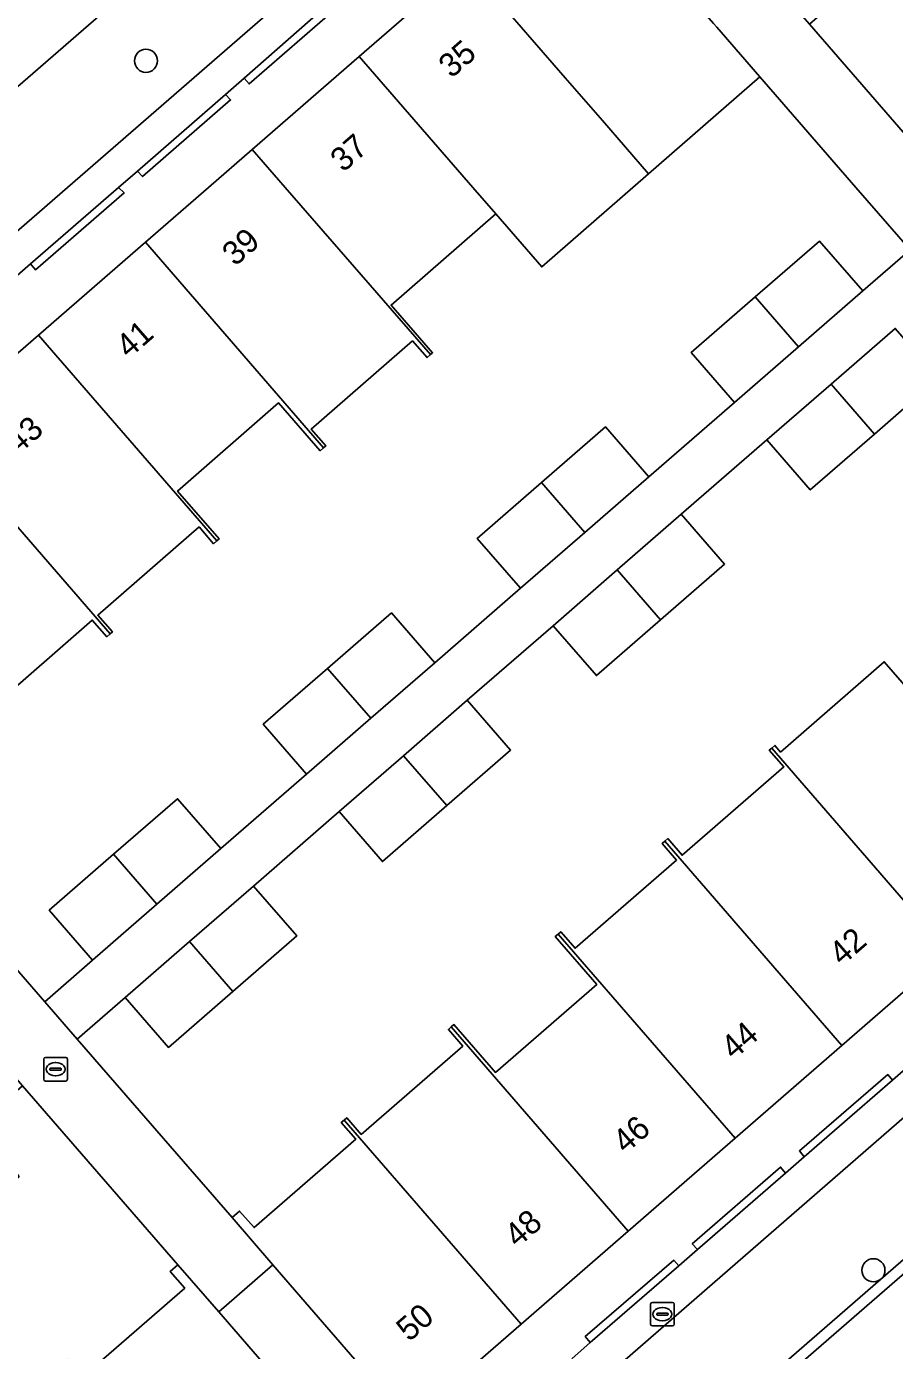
# Model space of a CAD drawing. Extents: x 155887 to 156869, y 383880 to 384678.
# Drawn here: x 156653.4 to 156690.1, y 384200.8 to 384256.8 of the extents above; entities that cross this region are included whole.
import ezdxf

# ---------------------------------------------------------------- set-up
doc = ezdxf.new("R2010")
doc.units = 0
for name, color, linetype in [('IMGEO_Boom', 7, 'Continuous'), ('IMGEO_Brandkraan', 7, 'Continuous'), ('IMGEO_Erf', 7, 'Continuous'), ('IMGEO_Kolk', 7, 'Continuous'), ('IMGEO_Muur', 7, 'Continuous'), ('IMGEO_Pand', 7, 'Continuous'), ('IMGEO_Pand_nummerreeks', 7, 'Continuous'), ('IMGEO_Pand_overbouw', 7, 'Continuous'), ('IMGEO_Parkeervlak_open', 7, 'Continuous'), ('IMGEO_Rijbaan_lokaal_gesloten', 7, 'Continuous'), ('IMGEO_Rijbaan_lokaal_open', 7, 'Continuous'), ('IMGEO_Voetpad_open', 7, 'Continuous')]:
    doc.layers.add(name, color=color, linetype=linetype)

msp = doc.modelspace()

# ---------------------------------------------------------------- linework, layer by layer
at = {"layer": 'IMGEO_Boom'}
for centre in [(156658.445, 384255.359), (156689.249, 384204.167)]:
    msp.add_circle(centre, 0.489, dxfattribs=at)
at = {"layer": 'IMGEO_Brandkraan'}
for p, q in [((156679.812, 384201.884), (156679.812, 384202.736)), ((156679.887, 384202.81), (156680.739, 384202.81)), ((156680.3, 384202.59), (156680.325, 384202.59)), ((156680.813, 384202.736), (156680.813, 384201.884)), ((156680.071, 384202.304), (156680.071, 384202.316)), ((156680.509, 384202.267), (156680.111, 384202.267)), ((156680.114, 384202.353), (156680.512, 384202.353)), ((156680.323, 384202.03), (156680.298, 384202.03)), ((156680.555, 384202.316), (156680.555, 384202.304)), ((156680.739, 384201.81), (156679.887, 384201.81))]:
    msp.add_line(p, q, dxfattribs=at)
for points in [[(156679.812, 384201.884), (156679.812, 384202.736)], [(156679.887, 384202.81), (156680.739, 384202.81)], [(156680.813, 384202.736), (156680.813, 384201.884)], [(156680.739, 384201.81), (156679.887, 384201.81)]]:
    msp.add_lwpolyline(points, dxfattribs=at)
for centre, radius, start, end in [((156679.889, 384202.734), 0.0765, 91.552, 178.448), ((156679.889, 384202.734), 0.0765, 91.552, 178.448), ((156680.737, 384202.734), 0.0765, 1.552, 88.448), ((156680.737, 384202.734), 0.0765, 1.552, 88.448), ((156679.889, 384201.886), 0.0765, 181.552, 268.448), ((156679.889, 384201.886), 0.0765, 181.552, 268.448), ((156680.111, 384202.313), 0.0403, 85.8775, 175.7526), ((156680.108, 384202.303), 0.0366, 178.938, 274.7102), ((156680.512, 384202.31), 0.043, 264.8664, 352.4533), ((156680.516, 384202.315), 0.0386, 1.7309, 96.639), ((156680.737, 384201.886), 0.0765, 271.552, 358.448), ((156680.737, 384201.886), 0.0765, 271.552, 358.448)]:
    msp.add_arc(centre, radius, start, end, dxfattribs=at)
for centre, major_axis, ratio, start_param, end_param in [((156680.299, 384202.31), (-0.387, 0.002), 0.722429, 4.712389, 7.853982), ((156680.324, 384202.31), (-0.39, 0.002), 0.717154, 1.570796, 4.712389)]:
    msp.add_ellipse(centre, major_axis=major_axis, ratio=ratio, start_param=start_param, end_param=end_param, dxfattribs=at)
at = {"layer": 'IMGEO_Erf'}
for points in [[(156690.542, 384261.628), (156686.251, 384257.898), (156686.867, 384257.189), (156686.542, 384256.907), (156692.537, 384250)], [(156649.367, 384239.821), (156653.889, 384243.746), (156658.419, 384247.678), (156661.093, 384250), (156662.948, 384251.61), (156667.478, 384255.543), (156672.007, 384259.474)], [(156666.555, 384257.634), (156662.809, 384254.38), (156662.601, 384254.619), (156661.815, 384253.939), (156662.026, 384253.701), (156658.302, 384250.456), (156658.085, 384250.694), (156657.286, 384249.99), (156657.517, 384249.764), (156653.773, 384246.507), (156653.551, 384246.761), (156652.762, 384246.068)], [(156647.654, 384223.021), (156654.157, 384215.535), (156656.183, 384217.295), (156654.348, 384219.408), (156657.073, 384221.774), (156659.782, 384224.127), (156661.617, 384222.014), (156665.248, 384225.166), (156663.413, 384227.28), (156666.134, 384229.642), (156668.84, 384231.992), (156670.675, 384229.879), (156674.306, 384233.032), (156672.471, 384235.145), (156675.189, 384237.505), (156677.905, 384239.864), (156679.741, 384237.751), (156683.364, 384240.897), (156681.528, 384243.01), (156684.247, 384245.371), (156686.963, 384247.729), (156688.798, 384245.616), (156690.803, 384247.359), (156688.507, 384250), (156684.438, 384254.685), (156679.727, 384250.579), (156675.205, 384246.638), (156673.255, 384248.886), (156668.821, 384245.022), (156670.58, 384243.004), (156670.487, 384242.923), (156670.346, 384242.799), (156669.727, 384243.506), (156665.441, 384239.769), (156666.057, 384239.062), (156665.965, 384238.981), (156665.823, 384238.857), (156664.063, 384240.876), (156659.783, 384237.145), (156661.542, 384235.126), (156661.446, 384235.042), (156661.307, 384234.921), (156660.69, 384235.629), (156656.402, 384231.893), (156657.02, 384231.184), (156656.93, 384231.106), (156656.785, 384230.979), (156656.167, 384231.687), (156651.88, 384227.951)], [(156692.007, 384241.92), (156689.29, 384239.56), (156686.572, 384237.2), (156684.737, 384239.314), (156681.114, 384236.168), (156682.949, 384234.054), (156680.231, 384231.694), (156677.515, 384229.335), (156675.68, 384231.448), (156672.049, 384228.296), (156673.884, 384226.182), (156671.179, 384223.833), (156668.457, 384221.469), (156666.622, 384223.583), (156662.992, 384220.43), (156664.827, 384218.317), (156662.116, 384215.963), (156659.392, 384213.597), (156657.557, 384215.711), (156655.532, 384213.952), (156662.094, 384206.399), (156662.411, 384206.675), (156663.022, 384205.974), (156667.324, 384209.714), (156666.714, 384210.416), (156666.837, 384210.523), (156666.948, 384210.62), (156667.559, 384209.919), (156671.861, 384213.659), (156671.251, 384214.361), (156671.371, 384214.465), (156671.485, 384214.565), (156673.244, 384212.543), (156677.531, 384216.27), (156675.773, 384218.293), (156675.895, 384218.4), (156676.007, 384218.497), (156676.618, 384217.796), (156680.913, 384221.53), (156680.303, 384222.232), (156680.415, 384222.33), (156680.537, 384222.436), (156681.148, 384221.735), (156685.45, 384225.475), (156684.84, 384226.177), (156684.942, 384226.266), (156685.074, 384226.381), (156685.317, 384226.102), (156689.709, 384229.924), (156691.225, 384228.177)], [(156692.447, 384217.618), (156687.917, 384213.685), (156683.396, 384209.76), (156678.867, 384205.828), (156674.33, 384201.888), (156669.908, 384198.049)], [(156676.476, 384200.422), (156677.253, 384201.108), (156677.043, 384201.361), (156680.793, 384204.593), (156681.013, 384204.352), (156681.794, 384205.052), (156681.58, 384205.281), (156685.317, 384208.535), (156685.53, 384208.285), (156686.317, 384208.971), (156686.118, 384209.218), (156689.853, 384212.454), (156690.06, 384212.211), (156690.852, 384212.91)], [(156655.795, 384199.686), (156660.088, 384203.414), (156659.473, 384204.123), (156659.791, 384204.399), (156653.217, 384211.97), (156651.237, 384210.251), (156653.074, 384208.138), (156650.355, 384205.775), (156647.64, 384203.415), (156645.803, 384205.528), (156642.18, 384202.379), (156644.017, 384200.266)]]:
    msp.add_lwpolyline(points, dxfattribs=at)
at = {"layer": 'IMGEO_Kolk'}
for p, q in [((156654.117, 384212.252), (156654.117, 384213.104)), ((156654.192, 384213.178), (156655.044, 384213.178)), ((156655.118, 384213.104), (156655.118, 384212.252)), ((156654.376, 384212.672), (156654.376, 384212.684)), ((156654.814, 384212.635), (156654.416, 384212.635)), ((156654.419, 384212.721), (156654.817, 384212.721)), ((156654.605, 384212.958), (156654.63, 384212.958)), ((156654.86, 384212.684), (156654.86, 384212.672)), ((156655.044, 384212.178), (156654.192, 384212.178)), ((156654.628, 384212.398), (156654.603, 384212.398))]:
    msp.add_line(p, q, dxfattribs=at)
for points in [[(156654.117, 384212.252), (156654.117, 384213.104)], [(156654.192, 384213.178), (156655.044, 384213.178)], [(156655.118, 384213.104), (156655.118, 384212.252)], [(156655.044, 384212.178), (156654.192, 384212.178)]]:
    msp.add_lwpolyline(points, dxfattribs=at)
for centre, radius, start, end in [((156654.194, 384213.102), 0.0765, 91.552, 178.448), ((156654.194, 384213.102), 0.0765, 91.552, 178.448), ((156655.042, 384213.102), 0.0765, 1.552, 88.448), ((156655.042, 384213.102), 0.0765, 1.552, 88.448), ((156654.416, 384212.681), 0.0403, 85.8775, 175.7526), ((156654.413, 384212.671), 0.0366, 178.938, 274.7102), ((156654.817, 384212.678), 0.043, 264.8664, 352.4533), ((156654.821, 384212.683), 0.0386, 1.7309, 96.639), ((156654.194, 384212.254), 0.0765, 181.552, 268.448), ((156654.194, 384212.254), 0.0765, 181.552, 268.448), ((156655.042, 384212.254), 0.0765, 271.552, 358.448), ((156655.042, 384212.254), 0.0765, 271.552, 358.448)]:
    msp.add_arc(centre, radius, start, end, dxfattribs=at)
for centre, major_axis, ratio, start_param, end_param in [((156654.604, 384212.678), (-0.387, 0.002), 0.722429, 4.712389, 7.853982), ((156654.629, 384212.678), (-0.39, 0.002), 0.717154, 1.570796, 4.712389)]:
    msp.add_ellipse(centre, major_axis=major_axis, ratio=ratio, start_param=start_param, end_param=end_param, dxfattribs=at)
at = {"layer": 'IMGEO_Muur'}
for points in [[(156662.601, 384254.619), (156662.809, 384254.38), (156666.555, 384257.634), (156666.334, 384257.89)], [(156658.085, 384250.694), (156658.302, 384250.456), (156662.026, 384253.701), (156661.815, 384253.939)], [(156653.551, 384246.761), (156653.773, 384246.507), (156657.517, 384249.764), (156657.286, 384249.99)], [(156690.06, 384212.211), (156689.853, 384212.454), (156686.118, 384209.218), (156686.317, 384208.971)], [(156685.53, 384208.285), (156685.317, 384208.535), (156681.58, 384205.281), (156681.794, 384205.052)], [(156681.013, 384204.352), (156680.793, 384204.593), (156677.043, 384201.361), (156677.253, 384201.108)]]:
    msp.add_lwpolyline(points, close=True, dxfattribs=at)
at = {"layer": 'IMGEO_Pand'}
for points in [[(156676.894, 384263.716), (156676.631, 384263.488), (156672.007, 384259.474), (156676.201, 384254.642), (156677.776, 384252.827), (156679.727, 384250.579), (156684.438, 384254.685), (156682.614, 384256.777), (156682.473, 384256.94), (156676.945, 384263.327), (156677.11, 384263.473)], [(156672.007, 384259.474), (156667.478, 384255.543), (156672.288, 384250), (156673.255, 384248.886), (156675.205, 384246.638), (156679.727, 384250.579), (156677.776, 384252.827), (156676.201, 384254.642)], [(156670.487, 384242.923), (156670.58, 384243.004), (156668.821, 384245.022), (156673.255, 384248.886), (156672.288, 384250), (156667.478, 384255.543), (156662.948, 384251.61), (156664.345, 384250)], [(156670.487, 384242.923), (156664.345, 384250), (156662.948, 384251.61), (156661.093, 384250), (156658.419, 384247.678), (156665.965, 384238.981), (156666.057, 384239.062), (156665.441, 384239.769), (156669.727, 384243.506), (156670.346, 384242.799)], [(156653.889, 384243.746), (156661.446, 384235.042), (156661.542, 384235.126), (156659.783, 384237.145), (156664.063, 384240.876), (156665.823, 384238.857), (156665.965, 384238.981), (156658.419, 384247.678)], [(156686.082, 384243.257), (156688.798, 384245.616), (156686.963, 384247.729), (156684.247, 384245.371)], [(156686.082, 384243.257), (156684.247, 384245.371), (156681.528, 384243.01), (156683.364, 384240.897)], [(156689.29, 384239.56), (156692.007, 384241.92), (156690.171, 384244.033), (156687.455, 384241.674)], [(156653.889, 384243.746), (156649.367, 384239.821), (156656.93, 384231.106), (156657.02, 384231.184), (156656.402, 384231.893), (156660.69, 384235.629), (156661.307, 384234.921), (156661.446, 384235.042)], [(156689.29, 384239.56), (156687.455, 384241.674), (156684.737, 384239.314), (156686.572, 384237.2)], [(156644.83, 384235.882), (156652.4, 384227.159), (156652.496, 384227.243), (156651.88, 384227.951), (156656.167, 384231.687), (156656.785, 384230.979), (156656.93, 384231.106), (156649.367, 384239.821)], [(156675.189, 384237.505), (156677.023, 384235.391), (156679.741, 384237.751), (156677.905, 384239.864)], [(156675.189, 384237.505), (156672.471, 384235.145), (156674.306, 384233.032), (156677.023, 384235.391)], [(156678.397, 384233.808), (156680.231, 384231.694), (156682.949, 384234.054), (156681.114, 384236.168)], [(156678.397, 384233.808), (156675.68, 384231.448), (156677.515, 384229.335), (156680.231, 384231.694)], [(156666.134, 384229.642), (156667.969, 384227.529), (156670.675, 384229.879), (156668.84, 384231.992)], [(156691.225, 384228.177), (156689.709, 384229.924), (156685.317, 384226.102), (156685.074, 384226.381), (156684.942, 384226.266), (156692.447, 384217.618), (156696.976, 384221.55)], [(156666.134, 384229.642), (156663.413, 384227.28), (156665.248, 384225.166), (156667.969, 384227.529)], [(156671.179, 384223.833), (156673.884, 384226.182), (156672.049, 384228.296), (156669.343, 384225.946)], [(156671.179, 384223.833), (156669.343, 384225.946), (156666.622, 384223.583), (156668.457, 384221.469)], [(156684.942, 384226.266), (156684.84, 384226.177), (156685.45, 384225.475), (156681.148, 384221.735), (156680.537, 384222.436), (156680.415, 384222.33), (156687.917, 384213.685), (156692.447, 384217.618)], [(156657.073, 384221.774), (156658.907, 384219.661), (156661.617, 384222.014), (156659.782, 384224.127)], [(156675.895, 384218.4), (156683.396, 384209.76), (156687.917, 384213.685), (156680.415, 384222.33), (156680.303, 384222.232), (156680.913, 384221.53), (156676.618, 384217.796), (156676.007, 384218.497)], [(156657.073, 384221.774), (156654.348, 384219.408), (156656.183, 384217.295), (156658.907, 384219.661)], [(156660.282, 384218.077), (156662.116, 384215.963), (156664.827, 384218.317), (156662.992, 384220.43)], [(156678.867, 384205.828), (156683.396, 384209.76), (156675.895, 384218.4), (156675.773, 384218.293), (156677.531, 384216.27), (156673.244, 384212.543), (156671.485, 384214.565), (156671.371, 384214.465)], [(156660.282, 384218.077), (156657.557, 384215.711), (156659.392, 384213.597), (156662.116, 384215.963)], [(156678.867, 384205.828), (156671.371, 384214.465), (156671.251, 384214.361), (156671.861, 384213.659), (156667.559, 384209.919), (156666.948, 384210.62), (156666.837, 384210.523), (156674.33, 384201.888)], [(156666.837, 384210.523), (156666.714, 384210.416), (156667.324, 384209.714), (156663.022, 384205.974), (156662.411, 384206.675), (156662.094, 384206.399), (156663.819, 384204.397), (156669.574, 384197.759), (156669.908, 384198.049), (156674.33, 384201.888)], [(156662.588, 384191.677), (156667.193, 384195.678), (156667.457, 384195.907), (156667.247, 384196.145), (156667.082, 384195.999), (156661.524, 384202.402), (156659.791, 384204.399), (156659.473, 384204.123), (156660.088, 384203.414), (156655.795, 384199.686), (156655.187, 384200.388), (156655.097, 384200.31)]]:
    msp.add_lwpolyline(points, close=True, dxfattribs=at)
at = {"layer": 'IMGEO_Pand_overbouw'}
msp.add_lwpolyline([(156661.524, 384202.402), (156667.082, 384195.999), (156667.247, 384196.145), (156667.457, 384195.907), (156669.574, 384197.759), (156663.819, 384204.397)], close=True, dxfattribs=at)
at = {"layer": 'IMGEO_Parkeervlak_open'}
for points in [[(156671.132, 384269.999), (156669.602, 384268.675), (156648.072, 384250), (156635.98, 384239.512), (156634.461, 384238.187), (156636.003, 384236.436), (156637.519, 384234.714), (156655.122, 384250), (156674.104, 384266.484), (156672.61, 384268.251)], [(156675.221, 384191.315), (156676.688, 384192.594), (156679.966, 384195.455), (156710.44, 384221.92), (156711.925, 384223.211), (156710.64, 384224.727), (156708.991, 384226.672), (156672.225, 384194.714), (156673.849, 384192.818)]]:
    msp.add_lwpolyline(points, close=True, dxfattribs=at)
at = {"layer": 'IMGEO_Rijbaan_lokaal_gesloten'}
for points in [[(156798.084, 384298.013), (156792.655, 384293.308), (156791.29, 384292.12), (156789.713, 384290.747), (156788.213, 384289.442), (156788.507, 384289.088), (156761.065, 384265.282), (156754.859, 384259.931), (156749.57, 384255.335), (156743.439, 384250), (156723.484, 384232.637), (156715.95, 384226.1), (156710.742, 384221.573), (156680.268, 384195.108), (156676.99, 384192.247), (156671.684, 384187.621), (156643.817, 384163.481), (156642.257, 384162.207), (156636.046, 384156.976), (156635.856, 384157.199), (156634.485, 384156.375)], [(156651.804, 384258.6), (156641.953, 384250), (156631.807, 384241.143), (156600.379, 384213.831), (156598.147, 384212.003), (156592.572, 384207.728), (156595.84, 384203.947), (156602.283, 384210.169), (156603.962, 384211.652), (156630.762, 384234.961), (156632.3, 384236.302), (156634.461, 384238.187), (156635.98, 384239.512), (156648.072, 384250), (156669.602, 384268.675)]]:
    msp.add_lwpolyline(points, dxfattribs=at)
at = {"layer": 'IMGEO_Rijbaan_lokaal_open'}
for points in [[(156634.485, 384156.375), (156635.856, 384157.199), (156636.046, 384156.976), (156642.257, 384162.207), (156643.817, 384163.481), (156671.684, 384187.621), (156676.99, 384192.247), (156680.268, 384195.108), (156710.742, 384221.573), (156715.95, 384226.1), (156723.484, 384232.637), (156743.439, 384250), (156749.57, 384255.335), (156754.859, 384259.931), (156761.065, 384265.282), (156788.507, 384289.088), (156788.213, 384289.442)], [(156788.213, 384289.442), (156760.764, 384265.63), (156754.558, 384260.279), (156753.039, 384258.959), (156750.769, 384256.987), (156749.268, 384255.682), (156742.738, 384250), (156723.182, 384232.984), (156715.648, 384226.447), (156714.132, 384225.13), (156711.925, 384223.211), (156710.44, 384221.92), (156679.966, 384195.455), (156676.688, 384192.594), (156675.221, 384191.315), (156672.872, 384189.267), (156671.382, 384187.968), (156643.521, 384163.833), (156641.976, 384162.571), (156636.1, 384157.623), (156635.92, 384157.835)]]:
    msp.add_lwpolyline(points, dxfattribs=at)
at = {"layer": 'IMGEO_Voetpad_open'}
for points in [[(156713.109, 384300.329), (156676.443, 384268.529), (156674.96, 384270.277), (156673.475, 384272.027), (156671.132, 384269.999), (156672.61, 384268.251), (156674.104, 384266.484), (156655.122, 384250), (156637.519, 384234.714), (156636.003, 384236.436), (156634.461, 384238.187), (156632.3, 384236.302), (156633.813, 384234.547), (156635.321, 384232.798), (156598.551, 384200.888), (156595.84, 384203.947)], [(156652.762, 384246.068), (156653.551, 384246.761), (156657.286, 384249.99), (156658.085, 384250.694), (156661.815, 384253.939), (156662.601, 384254.619), (156666.334, 384257.89)], [(156690.803, 384247.359), (156688.798, 384245.616), (156686.082, 384243.257), (156683.364, 384240.897), (156679.741, 384237.751), (156677.023, 384235.391), (156674.306, 384233.032), (156670.675, 384229.879), (156667.969, 384227.529), (156665.248, 384225.166), (156661.617, 384222.014), (156658.907, 384219.661), (156656.183, 384217.295), (156654.157, 384215.535), (156655.532, 384213.952), (156657.557, 384215.711), (156660.282, 384218.077), (156662.992, 384220.43), (156666.622, 384223.583), (156669.343, 384225.946), (156672.049, 384228.296), (156675.68, 384231.448), (156678.397, 384233.808), (156681.114, 384236.168), (156684.737, 384239.314), (156687.455, 384241.674), (156690.171, 384244.033)], [(156633.306, 384160.897), (156669.903, 384192.706), (156671.568, 384190.778), (156672.872, 384189.267), (156675.221, 384191.315), (156673.849, 384192.818), (156672.225, 384194.714), (156708.991, 384226.672)], [(156690.852, 384212.91), (156690.06, 384212.211), (156686.317, 384208.971), (156685.53, 384208.285), (156681.794, 384205.052), (156681.013, 384204.352), (156677.253, 384201.108), (156676.476, 384200.422)]]:
    msp.add_lwpolyline(points, dxfattribs=at)
for points in [[(156702.629, 384238.373), (156694.473, 384247.77), (156693.1, 384249.352), (156692.537, 384250), (156686.542, 384256.907), (156684.764, 384258.95), (156679.025, 384265.545), (156676.894, 384263.716), (156677.11, 384263.473), (156676.945, 384263.327), (156682.473, 384256.94), (156682.614, 384256.777), (156684.438, 384254.685), (156688.507, 384250), (156690.803, 384247.359), (156692.178, 384245.777), (156698.727, 384238.245), (156700.467, 384236.231), (156706.022, 384229.824), (156706.188, 384229.966), (156706.391, 384229.725), (156708.523, 384231.58), (156702.763, 384238.219)], [(156655.532, 384213.952), (156654.157, 384215.535), (156647.654, 384223.021), (156646.03, 384224.891), (156645.828, 384225.123), (156640.066, 384231.747), (156637.941, 384229.874), (156638.154, 384229.632), (156637.988, 384229.487), (156643.552, 384223.098), (156645.299, 384221.092), (156651.84, 384213.557), (156653.217, 384211.97), (156659.791, 384204.399), (156661.524, 384202.402), (156667.082, 384195.999), (156667.247, 384196.145), (156667.457, 384195.907), (156669.574, 384197.759), (156663.819, 384204.397), (156662.094, 384206.399)]]:
    msp.add_lwpolyline(points, close=True, dxfattribs=at)

# ---------------------------------------------------------------- texts
at = {"layer": 'IMGEO_Pand_nummerreeks'}
for s, rotation, p in [('35', 40.9608, (156671.382, 384254.589)), ('37', 40.9603, (156666.799, 384250.61)), ('39', 40.9603, (156662.216, 384246.632)), ('41', 40.9603, (156657.718, 384242.727)), ('43', 40.9603, (156653.05, 384238.675)), ('42', 40.9658, (156687.915, 384217.021)), ('44', 40.9658, (156683.335, 384213.045)), ('46', 40.9658, (156678.753, 384209.067)), ('48', 40.9658, (156674.173, 384205.091)), ('50', 40.9658, (156669.591, 384201.113))]:
    msp.add_text(s, height=1, rotation=rotation, dxfattribs=at).set_placement(p)

doc.saveas('drawing.dxf')
